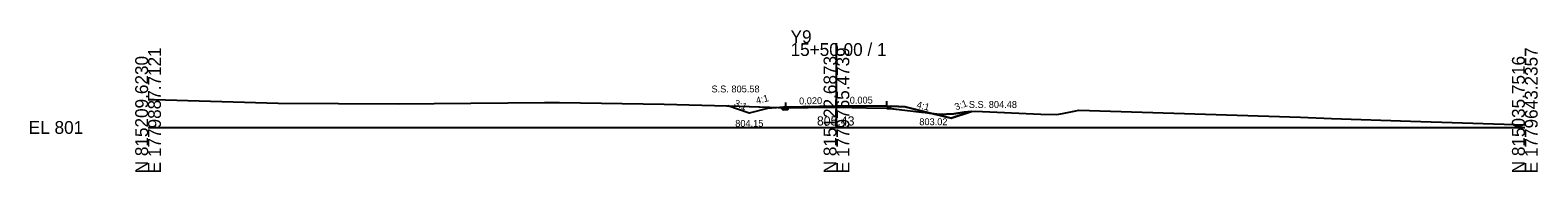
# Model space of a CAD drawing. Extents: x -26 to 1303, y -10 to 9523.
# Drawn here: x -25.7 to 302.8, y 8990.3 to 9021.2 of the extents above; entities that cross this region are included whole.
import ezdxf

# ---------------------------------------------------------------- set-up
doc = ezdxf.new("R2010")
doc.units = 0
for name, color, linetype in [('Exist Cross Section Cell', 7, 'Continuous'), ('Exist XS Center Line Elevation Label', 7, 'Continuous'), ('Exist XS Ground Line', 7, 'Continuous'), ('Prop XS Ditch Slope Text', 7, 'Continuous'), ('Prop XS Ditch Standard Text', 7, 'Continuous'), ('Prop XS Dump Level', 7, 'Continuous'), ('Prop XS Earthwork Shape', 7, 'Continuous'), ('Prop XS EOT Tick Mark', 7, 'Continuous'), ('Prop XS Finish Grade', 7, 'Continuous'), ('Prop XS Finish Grade Earthwork', 7, 'Continuous'), ('Prop XS Finish Grade Pavement', 7, 'Continuous'), ('Prop XS Pvmt Edge Slope', 7, 'Continuous'), ('Prop XS SE Text', 7, 'Continuous'), ('Prop XS Side Slope Text', 7, 'Continuous'), ('Prop XS SS Elevation Text', 7, 'Continuous'), ('Prop XS Subgrade Earthwork', 7, 'Continuous'), ('Scratch_Level_4', 7, 'Continuous')]:
    doc.layers.add(name, color=color, linetype=linetype)

msp = doc.modelspace()

# ---------------------------------------------------------------- linework, layer by layer
at = {"layer": 'Exist Cross Section Cell'}
for p, q in [((150, 9000), (150, 9018.41)), ((0, 9000), (150, 9000)), ((150, 9000), (300, 9000))]:
    msp.add_line(p, q, dxfattribs=at)
at = {"layer": 'Exist XS Ground Line'}
for p, q in [((0, 9006.13), (1.3, 9006.14)), ((1.3, 9006.14), (28.37, 9005.31)), ((28.37, 9005.31), (54.67, 9005.18)), ((54.67, 9005.18), (62.35, 9005.26)), ((62.35, 9005.26), (86.36, 9005.43)), ((86.36, 9005.43), (87.87, 9005.45)), ((87.87, 9005.45), (88.28, 9005.44)), ((88.28, 9005.44), (89.68, 9005.42)), ((89.68, 9005.42), (112.45, 9005.11)), ((112.45, 9005.11), (128.91, 9004.62)), ((128.91, 9004.62), (139.41, 9004.31)), ((139.41, 9004.31), (143.86, 9004.38)), ((143.86, 9004.38), (150.13, 9004.43)), ((150.13, 9004.43), (156.55, 9004.3)), ((156.55, 9004.3), (161.33, 9004.2)), ((161.33, 9004.2), (163.64, 9003.93)), ((163.64, 9003.93), (168.56, 9003.33)), ((168.56, 9003.33), (169.35, 9003.28)), ((169.35, 9003.28), (172.41, 9002.84)), ((172.41, 9002.84), (175.55, 9003)), ((175.55, 9003), (177.83, 9003.35)), ((177.83, 9003.35), (180.21, 9003.54)), ((180.21, 9003.54), (194.56, 9002.88)), ((194.56, 9002.88), (197.99, 9002.81)), ((197.99, 9002.81), (199.23, 9003.08)), ((199.23, 9003.08), (202.16, 9003.66)), ((202.16, 9003.66), (202.84, 9003.79)), ((202.84, 9003.79), (251.11, 9002.27)), ((251.11, 9002.27), (257.89, 9001.98)), ((257.89, 9001.98), (275.07, 9001.38)), ((275.07, 9001.38), (300, 9000.61))]:
    msp.add_line(p, q, dxfattribs=at)
at = {"layer": 'Prop XS Dump Level'}
for p, q in [((139, 9004.47), (150, 9004.69)), ((150, 9004.69), (161, 9004.74))]:
    msp.add_line(p, q, dxfattribs=at)
at = {"layer": 'Prop XS Earthwork Shape'}
for points in [[(126.35, 9004.7), (128.91, 9004.62), (137.66, 9004.36), (135, 9004.15), (131, 9003.15)], [(137.66, 9004.36), (137.92, 9004.35), (137.9, 9004.38)], [(138.4, 9003.87), (139.41, 9003.89), (139.41, 9004.31), (137.92, 9004.35)], [(161, 9004.16), (161, 9004.2), (161.33, 9004.2), (161.58, 9004.16)], [(169.35, 9003.28), (170.81, 9003.07), (165, 9004.52), (162.1, 9004.68), (161.58, 9004.16), (163.64, 9003.93), (168.56, 9003.33)], [(170.81, 9003.07), (175.02, 9002.02), (179.4, 9003.48), (177.83, 9003.35), (175.55, 9003), (172.41, 9002.84)]]:
    msp.add_lwpolyline(points, close=True, dxfattribs=at)
at = {"layer": 'Prop XS EOT Tick Mark'}
for p, q in [((139, 9004.47), (139, 9005.47)), ((161, 9004.74), (161, 9005.74))]:
    msp.add_line(p, q, dxfattribs=at)
at = {"layer": 'Prop XS Finish Grade'}
for p, q in [((139, 9004.47), (137.9, 9004.38)), ((161, 9004.74), (162.1, 9004.68))]:
    msp.add_line(p, q, dxfattribs=at)
at = {"layer": 'Prop XS Finish Grade Earthwork'}
for p, q in [((131, 9003.15), (126.35, 9004.7)), ((135, 9004.15), (131, 9003.15)), ((137.9, 9004.38), (135, 9004.15)), ((162.1, 9004.68), (165, 9004.52)), ((165, 9004.52), (175.02, 9002.02)), ((175.02, 9002.02), (179.4, 9003.48))]:
    msp.add_line(p, q, dxfattribs=at)
at = {"layer": 'Prop XS Finish Grade Pavement'}
for p, q in [((139, 9004.47), (150, 9004.69)), ((150, 9004.69), (161, 9004.74))]:
    msp.add_line(p, q, dxfattribs=at)
at = {"layer": 'Prop XS Pvmt Edge Slope'}
for p, q in [((139, 9004.47), (138.4, 9003.87)), ((161, 9004.74), (161.58, 9004.16))]:
    msp.add_line(p, q, dxfattribs=at)
at = {"layer": 'Prop XS Subgrade Earthwork'}
for p, q in [((138.4, 9003.87), (137.9, 9004.38)), ((138.4, 9003.87), (139.41, 9003.89)), ((139.41, 9003.89), (139.41, 9004.31)), ((161, 9004.16), (161, 9004.2)), ((161, 9004.16), (161.58, 9004.16)), ((161.58, 9004.16), (162.1, 9004.68))]:
    msp.add_line(p, q, dxfattribs=at)
at = {"layer": 'Scratch_Level_4'}
for points in [[(137.66, 9004.36), (135, 9004.15), (131, 9003.15), (126.35, 9004.7), (128.91, 9004.62)], [(137.92, 9004.35), (139.41, 9004.31), (139.41, 9003.89), (138.4, 9003.87)], [(161, 9004.16), (161.58, 9004.16), (161.33, 9004.2), (161, 9004.2)], [(172.41, 9002.84), (175.55, 9003), (177.83, 9003.35), (179.4, 9003.48), (175.02, 9002.02), (170.81, 9003.07)]]:
    msp.add_lwpolyline(points, close=True, dxfattribs=at)

# ---------------------------------------------------------------- texts
at = {"layer": 'Exist Cross Section Cell'}
for s, p in [('Y9', (140, 9018.41)), ('15+50.00 / 1', (140, 9015.61)), ('EL 801', (-26, 8998.6))]:
    msp.add_text(s, height=2.8, dxfattribs=at).set_placement(p)
for s, p in [('N 815209.6230', (0, 8990)), ('E 1779887.7121', (2.8, 8990)), ('N 815122.6873', (150, 8990)), ('E 1779765.4739', (152.8, 8990)), ('N 815035.7516', (300, 8990)), ('E 1779643.2357', (302.8, 8990))]:
    msp.add_text(s, height=2.8, rotation=90, dxfattribs=at).set_placement(p)
at = {"layer": 'Exist XS Center Line Elevation Label'}
msp.add_text('805.43', height=2, dxfattribs=at).set_placement((145.75, 9000.43))
at = {"layer": 'Prop XS Ditch Slope Text'}
for rotation, p in [(14.0362, (132.64, 9005.1)), (345.9638, (167.38, 9004.32))]:
    msp.add_text('4:1', height=1.5, rotation=rotation, dxfattribs=at).set_placement(p)
at = {"layer": 'Prop XS Ditch Standard Text'}
for s, p in [('803.02', (168.06, 9000.5)), ('804.15', (127.95, 9000.15))]:
    msp.add_text(s, height=1.5, dxfattribs=at).set_placement(p)
at = {"layer": 'Prop XS Dump Level'}
for s, height, p in [('Case1', 0.04, (135, 9004.11)), ('Eop', 0.3, (139.41, 9004.01)), ('Eop', 0.3, (161.33, 9003.9)), ('Case1', 0.04, (165, 9004.48))]:
    msp.add_text(s, height=height, dxfattribs=at).set_placement(p)
at = {"layer": 'Prop XS SE Text'}
for s, rotation, p in [('0.020', 1.1458, (141.88, 9005.03)), ('0.005', 0.2865, (152.9, 9005.2))]:
    msp.add_text(s, height=1.5, rotation=rotation, dxfattribs=at).set_placement(p)
at = {"layer": 'Prop XS Side Slope Text'}
for rotation, p in [(337.6812, (127.55, 9004.77)), (20.6648, (176.08, 9003.71))]:
    msp.add_text('3:1', height=1.5, rotation=rotation, dxfattribs=at).set_placement(p)
at = {"layer": 'Prop XS SS Elevation Text'}
for s, p in [('S.S. 805.58', (122.77, 9007.65)), ('S.S. 804.48', (178.85, 9004.27))]:
    msp.add_text(s, height=1.5, dxfattribs=at).set_placement(p)

doc.saveas('drawing.dxf')
